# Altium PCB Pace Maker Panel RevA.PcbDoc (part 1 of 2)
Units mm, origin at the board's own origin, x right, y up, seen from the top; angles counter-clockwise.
Board outline 150.47 x 78.27 mm, 2 copper layers (Top Copper, Bottom Copper), stack 1.57 mm thick; 193 components, 124 nets, 564 pads, 154 vias.
Unrouted connection lines stored in the file: 2.
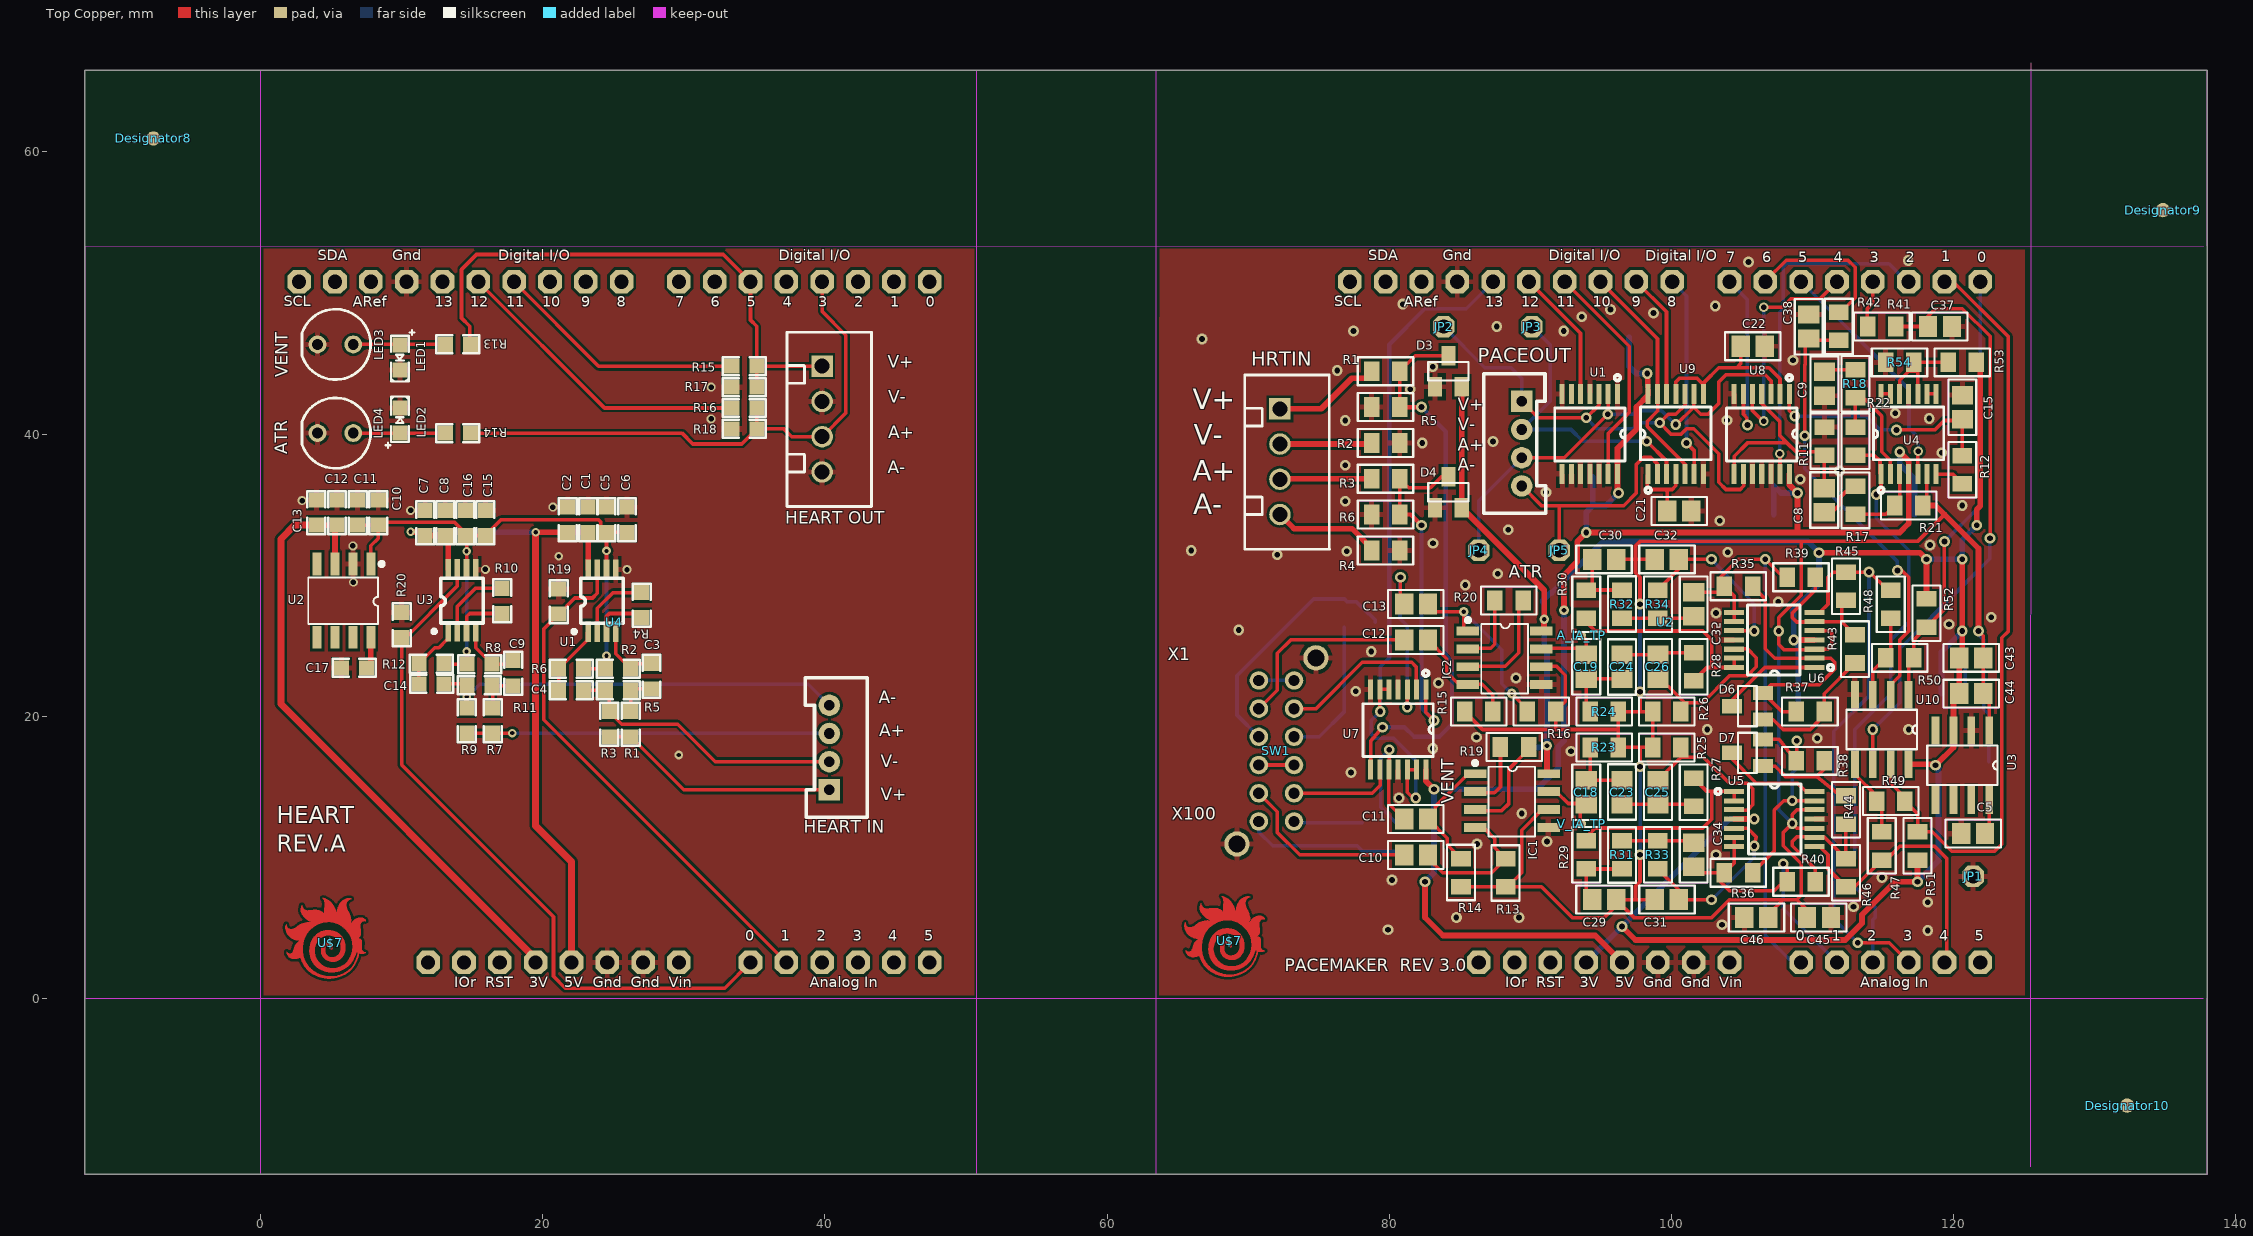
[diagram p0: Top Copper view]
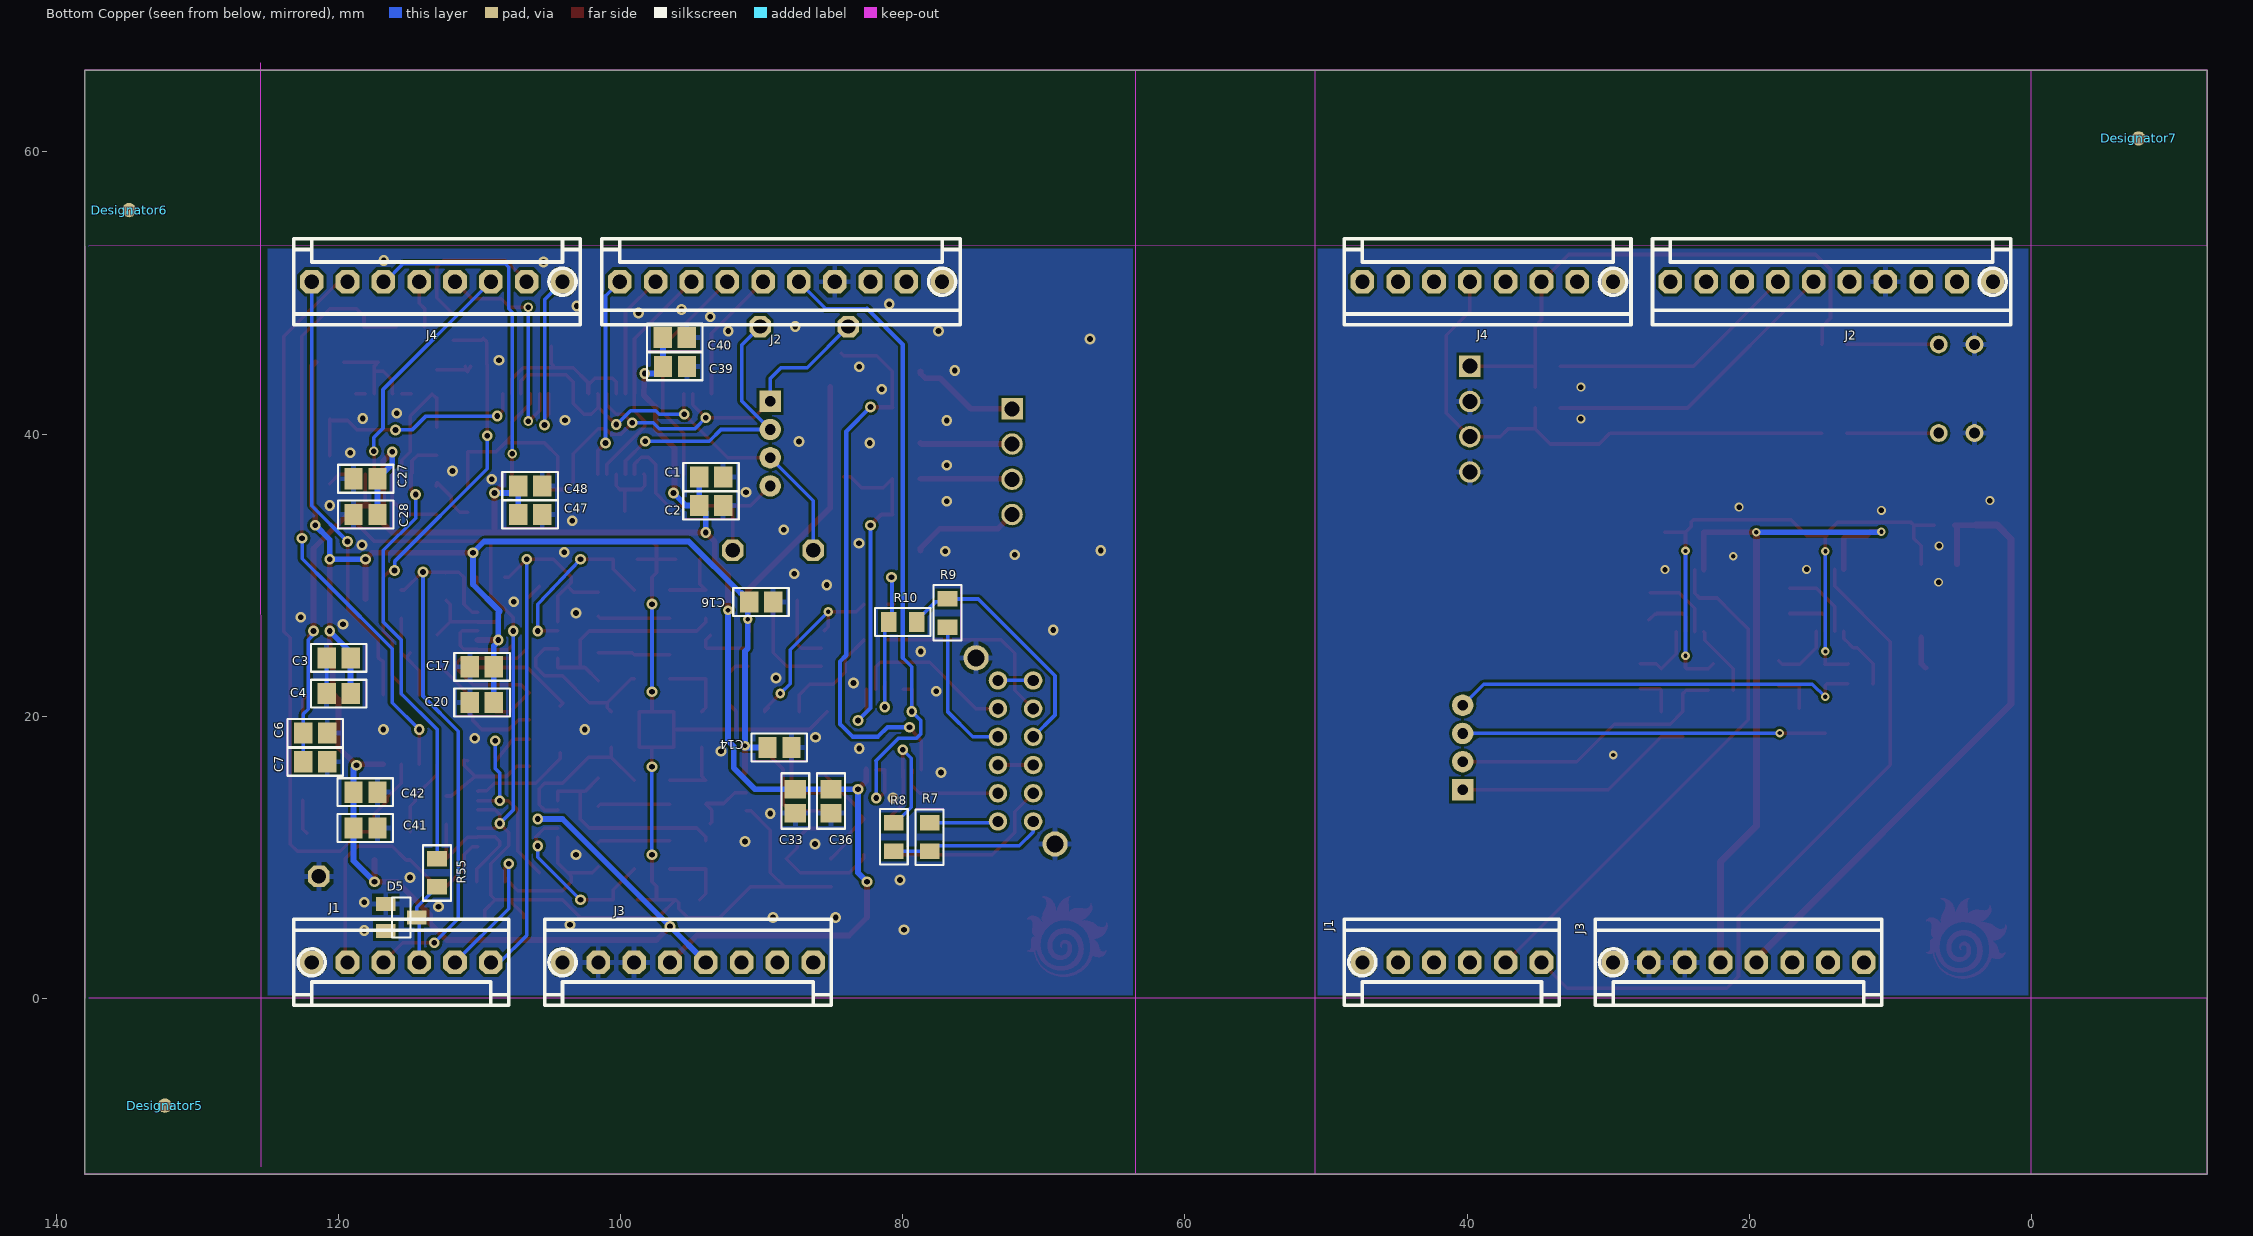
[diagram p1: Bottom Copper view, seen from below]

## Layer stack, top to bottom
Top Mask: solder mask 0.015, Solder Resist, Dk 3.8
Top Copper: signal copper 0.035
Dielectric 1: prepreg 0.1, 2313, Dk 4.05
Core: core 1.3, FR-4, Dk 4.5
Dielectric 2: prepreg 0.1, 2313, Dk 4.05
Bottom Copper: signal copper 0.035
Bottom Mask: solder mask 0.015, Solder Resist, Dk 3.8

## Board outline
-12.471,0 -12.471,53.33 -12.471,65.801 137.998,65.801 137.998,53.33 137.998,0 137.998,-12.471 -12.471,-12.471

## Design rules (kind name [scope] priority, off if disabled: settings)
AssemblyTestPointUsage [All] p1 off:
AssemblyTestpoint [All] p1 off: testpointundercomponent=TRUE minsize=1.016 maxsize=2.54 preferedsize=1.524 minholesize=0 maxholesize=1.016 preferedholesize=0.813 testpointgrid=0.025 usegrid=TRUE gridtolerance=0 allowsidetop=TRUE allowsidebottom=TRUE
Clearance Clearance_poly [InPolygon vs InPolygon] p1: gap=0.254 ignorepadtopadclearanceinfootprint=FALSE
Clearance [All] p2: gap=0.152 ignorepadtopadclearanceinfootprint=FALSE
ComponentClearance [All] p1 off: gap=0.254 collisioncheckmode=3 verticalgap=0.254 showdistances=FALSE
DiffPairsRouting [All] p1 off: maxlimit=0.254 minlimit=0.254 mostfreqgap=0.254 toplayer_minwidth=0.381 toplayer_maxwidth=0.381 toplayer_prefwidth=0.381 bottomlayer_minwidth=0.381 bottomlayer_maxwidth=0.381 bottomlayer_prefwidth=0.381 maxuncoupledlength=12.7
FabricationTestPointUsage [All] p1 off: valid=0 allowmultiple=FALSE
FabricationTestpoint [All] p1 off: side=3 testpointundercomponent=TRUE minsize=1.016 maxsize=2.54 preferedsize=1.524 minholesize=0 maxholesize=1.016 preferedholesize=0.813 testpointgrid=0.025 allowsidetop=TRUE allowsidebottom=TRUE usegrid=TRUE gridtolerance=0
FanoutControl Fanout_BGA [IsBGA] p1 off: bgadir=Out bgaviamode=Centered fanoutstyle=Auto fanoutdirection=Alternating viagrid=0.025 // Fanout_BGA (Default Rule)
FanoutControl Fanout_LCC [IsLCC] p2 off: bgadir=Out bgaviamode=Centered fanoutstyle=Auto fanoutdirection=Alternating viagrid=0.025 // Fanout_LCC (Default Rule)
FanoutControl Fanout_SOIC [IsSOIC] p3 off: bgadir=Out bgaviamode=Centered fanoutstyle=Auto fanoutdirection=Alternating viagrid=0.025 // Fanout_SOIC (Default Rule)
FanoutControl Fanout_Small [(CompPinCount < 5)] p4 off: bgadir=Out bgaviamode=Centered fanoutstyle=Auto fanoutdirection=OutThenIn viagrid=0.025 // Fanout_Small (Default Rule)
FanoutControl Fanout_Default [All] p5 off: bgadir=Out bgaviamode=Centered fanoutstyle=Auto fanoutdirection=Alternating viagrid=0.025 // Fanout_Default (Default Rule)
Height [All] p1 off: minheight=0 maxheight=25.4 prefheight=12.7
HoleSize [All] p1: absolutevalues=TRUE maxlimit=6 minlimit=0.025 maxpercent=80.000 minpercent=20.000
MinimumSolderMaskSliver [All] p1 off: minsoldermaskwidth=0.254
PolygonConnect PolygonConnect_via [IsVia] p1: connectstyle=Direct reliefconductorwidth=0.254 reliefentries=4 polygonreliefangle="90 Angle" airgapwidth=0.254
PolygonConnect [All] p2: connectstyle=Relief reliefconductorwidth=0.381 reliefentries=4 polygonreliefangle="90 Angle" airgapwidth=0.203
RoutingPriority [All] p1 off: routingpriority=0
RoutingTopology [All] p1 off: topology=Shortest
RoutingVias [All] p1: holewidth=0.381 width=0.635 viastyle="Through Hole" minholewidth=0.305 minwidth=0.61 maxholewidth=1.524 maxwidth=2.032
SilkToSilkClearance [All] p1 off: silktosilkclearance=0.254
SilkToSolderMaskClearance [IsPad] p1 off: minsilkscreentomaskgap=0.254 clearancetoexposedcopper=TRUE
SolderMaskExpansion [All] p1: expansion=0.102 istentingtop=FALSE
UnRoutedNet UnRoutedNet_signal [All] p1:
UnpouredPolygon [All] p1 off:
Width [All] p1: maxlimit=2.032 minlimit=0.203 preferedwidth=0.203
10 further rules are at their usual default settings.

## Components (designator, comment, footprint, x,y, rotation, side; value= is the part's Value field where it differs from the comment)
A_IA_TP "TPSTP06R" TP06R 93.662,25.717 r0 top
C1 "*" C0805 93.599,36.957 r180 bottom value=0.1uF
C1 "0.1uF" 0603_N_1MM 23.21,34.812 r270 top value=CL10B104KB8NNNL
C2 "*" C0805 93.599,34.925 r180 bottom value=1uF
C2 "1uF" 0603_N 21.761,34.812 r270 top value=CL10B105KQ8NNNC
C3 "*" C0805 120.015,24.13 r0 bottom value=0.1uF
C3 "3300pF" 0603_N 27.699,21.935 r90 top value=885012006016
C4 "*" C0805 120.015,21.59 r0 bottom value=1uF
C4 "3300pF" 0603_N 22.891,21.834 r180 top value=885012006016
C5 "*" C0805 121.412,11.684 r180 top value=1uF
C5 "0.1uF" 0603_N_1MM 24.511,34.812 r270 top value=CL10B104KB8NNNL
C6 "*" C0805 121.666,18.796 r180 bottom value=0.1uF
C6 "1uF" 0603_N 25.961,34.812 r270 top value=CL10B105KQ8NNNC
C7 "*" C0805 121.666,16.764 r180 bottom value=1uF
C7 "0.1uF" 0603_N_1MM 11.652,34.584 r270 top value=CL10B104KB8NNNL
C8 "*" C0805 110.858,35.306 r270 top value=1uF
C8 "1uF" 0603_N 13.074,34.584 r270 top value=CL10B105KQ8NNNC
C9 "*" C0805 110.871,43.561 r90 top value=1uF
C9 "3300pF" 0603_N 17.892,22.149 r90 top value=885012006016
C10 "*" C0805 81.915,10.16 r0 top value=10uF
C10 "0.1uF" 0603_N_1MM 8.324,35.32 r270 top value=CL10B104KB8NNNL
C11 "*" C0805 81.915,12.7 r0 top value=10uF
C11 "1uF" 0603_N 6.862,35.32 r270 top value=CL10B105KQ8NNNC
C12 "*" C0805 81.915,25.4 r0 top value=10uF
C12 "0.1uF" 0603_N_1MM 5.399,35.32 r270 top value=CL10B104KB8NNNL
C13 "*" C0805 81.915,27.94 r0 top value=10uF
C13 "1uF" 0603_N 3.937,35.32 r270 top value=CL10B105KQ8NNNC
C14 "*" C0805 88.75,17.78 r180 bottom value=0.1uF
C14 "3300pF" 0603_N 12.998,22.288 r180 top value=885012006016
C15 "*" C0805 120.65,41.91 r90 top value=1uF
C15 "0.1uF" 0603_N_1MM 15.919,34.584 r270 top value=CL10B104KB8NNNL
C16 "*" C0805 90.05,28.1 r180 bottom value=1uF
C16 "1uF" 0603_N 14.496,34.584 r270 top value=CL10B105KQ8NNNC
C17 "*" C0805 109.855,23.495 r0 bottom value=0.1uF
C17 "1uF" 0603_N 5.719,23.419 r0 top value=CL10B105KQ8NNNC
C18 "*" C0805 93.98,14.605 r90 top value=10uF
C19 "*" C0805 93.98,23.495 r270 top value=10uF
C20 "*" C0805 109.855,20.955 r0 bottom value=1uF
C21 "*" C0805 100.584,34.544 r0 top value=10uF
C22 "*" C0805 105.791,46.228 r0 top value=10uF
C23 "*" C0805 96.52,14.605 r270 top value=1.5uF
C24 "*" C0805 96.52,23.495 r90 top value=1.5uF
C25 "*" C0805 99.06,14.605 r90 top value=1.5uF
C26 "*" C0805 99.06,23.495 r270 top value=10uF
C27 "*" C0805 118.11,36.83 r0 bottom value=0.1uF
C28 "*" C0805 118.11,34.29 r0 bottom value=1uF
C29 "*" C0805 95.25,6.985 r0 top value=0.1uF
C30 "*" C0805 95.25,31.115 r0 top value=0.1uF
C31 "*" C0805 99.695,6.985 r180 top value=0.039uF
C32 "*" C0805 99.695,31.115 r180 top value=0.022uF
C33 "*" C0805 87.63,13.97 r270 bottom value=0.1uF
C34 "*" C0805 101.6,10.16 r270 top value=0.39uF
C35 "*" C0805 101.6,27.94 r90 top value=0.22uF
C36 "*" C0805 85.09,13.97 r270 bottom value=1uF
C37 "*" C0805 119.062,47.625 r0 top value=1uF
C38 "*" C0805 109.753,47.625 r90 top value=1uF
C39 "*" C0805 96.166,44.801 r180 bottom value=0.1uF
C40 "*" C0805 96.177,46.855 r180 bottom value=1uF
C41 "*" C0805 118.11,12.065 r180 bottom value=0.1uF
C42 "*" C0805 118.11,14.605 r180 bottom value=1uF
C43 "*" C0805 121.285,24.13 r0 top value=0.1uF
C44 "*" C0805 121.285,21.59 r0 top value=1uF
C45 "*" C0805 110.49,5.715 r0 top value=1uF
C46 "*" C0805 106.045,5.715 r180 top value=0.1uF
C47 "*" C0805 106.426,34.29 r180 bottom value=1uF
C48 "*" C0805 106.426,36.322 r180 bottom value=0.1uF
D3 "BAT54S" SOT23 84.201,44.45 r0 top
D4 "BAT54S" SOT23 84.201,35.877 r0 top
D5 "*" SOT23 115.57,5.715 r270 bottom value=BZX84C3V3LT1G
D6 "BAT54S" SOT23 105.41,20.701 r90 top
D7 "BAT54S" SOT23 105.41,17.399 r90 top
Designator5 "Comment" Fiducial_40_100#1 132.334,-7.62 r180 bottom
Designator6 "Comment" Fiducial_40_100#1 134.874,55.88 r180 bottom
Designator7 "Comment" Fiducial_40_100#1 -7.62,60.96 r180 bottom
Designator8 "Comment" Fiducial_40_100#1 -7.62,60.96 r0 top
Designator9 "Comment" Fiducial_40_100#2 134.874,55.88 r180 bottom
Designator10 "Comment" Fiducial_40_100#2 132.334,-7.62 r180 bottom
"HEART IN" "B4B-PH-K-S" B4B-PH-K-S 40.31,15.769 r90 top
"HEART OUT" "B4B-XH-A" B4B-XH-A 39.802,44.813 r270 top value=B4B-XH-A(LF)(SN)
HRTIN "B4B-XH-A" B4B-XH-A 72.263,41.79 r270 top
IC1 "AD8226" SOIC8_SMTC 86.1,15.91 r0 top
IC2 "AD8226" SOIC8_SMTC 85.593,26.04 r0 top
J1 "LHS-06-TS" LHS-00-TS_OUTLINE 121.92,2.54 r0 bottom
J1 "LHS-06-TS" LHS-00-TS_OUTLINE 47.422,2.54 r0 bottom
J2 "LHS-10-TS" LHS-10-TS_OUTLINE 77.216,50.8 r180 bottom
J2 "LHS-10-TS" LHS-10-TS_OUTLINE 2.718,50.8 r180 bottom
J3 "LHS-08-TS" LHS-08-TS_OUTLINE 104.14,2.54 r0 bottom
J3 "LHS-08-TS" LHS-08-TS_OUTLINE 29.642,2.54 r0 bottom
J4 "LHS-08-TS" LHS-08-TS_OUTLINE 104.14,50.8 r180 bottom
J4 "LHS-08-TS" LHS-08-TS_OUTLINE 29.642,50.8 r180 bottom
JP1 "PINHD-1X1" 1X01 121.412,8.636 r0 top
JP2 "PINHD-1X1" 1X01 83.87,47.625 r0 top
JP3 "PINHD-1X1" 1X01 90.12,47.625 r0 top
JP4 "PINHD-1X1" 1X01 86.36,31.75 r0 top
JP5 "PINHD-1X1" 1X01 92.075,31.75 r0 top
LED1 "VLMB1300-GS08" LED_0603 9.855,46.33 r270 top
LED2 "SML-D12V1WT86" LED_0603 9.855,40.068 r90 top
LED3 "151051BS04000" LED_5mm 5.288,46.355 r0 top
LED4 "151051RS11000" LED_5mm 5.288,40.068 r0 top
PACEOUT "B4B-PH-K-S" B4B-PH-K-S 89.408,41.322 r270 top value=B4B-XH-A
R1 "*" R0805 79.756,44.45 r0 top value=59
R1 "75K" 0603_N_RES 26.226,20.31 r270 top value=RC0603FR-0775KL
R2 "*" R0805 79.756,39.37 r0 top value=59
R2 "162K" 0603_N_RES 24.447,23.358 r0 top value=RC0603FR-07162KL
R3 "*" R0805 79.756,36.83 r0 top value=59
R3 "1K" 0603_N_RES 24.717,20.31 r270 top value=RC0603FR-071KL
R4 "*" R0805 79.756,31.75 r0 top value=59
R4 "49.9K" 0603_N_RES 27,28.753 r270 top value=RC0603FR-0749K9L
R5 "*" R0805 79.756,41.91 r0 top value=1M
R5 "49.9K" 0603_N_RES 24.447,21.834 r0 top value=RC0603FR-0749K9L
R6 "*" R0805 79.756,34.29 r0 top value=1M
R6 "162K" 0603_N_RES 21.113,23.358 r0 top value=RC0603FR-07162KL
R7 "*" R0805 78.105,11.43 r90 bottom value=100k
R7 "75K" 0603_N_RES 16.434,20.561 r270 top value=RC0603FR-0775KL
R8 "*" R0805 80.645,11.43 r270 bottom value=1k
R8 "162K" 0603_N_RES 14.623,23.678 r0 top value=RC0603FR-07162KL
R9 "*" R0805 76.835,27.305 r270 bottom value=100k
R9 "1K" 0603_N_RES 14.605,20.561 r270 top value=RC0603FR-071KL
R10 "*" R0805 80.01,26.67 r180 bottom value=1k
R10 "49.9K" 0603_N_RES 17.109,29.055 r270 top value=RC0603FR-0749K9L
R11 "*" R0805 110.871,39.497 r270 top value=5.49k
R11 "49.9K" 0603_N_RES 14.605,22.186 r0 top value=RC0603FR-0749K9L
R12 "*" R0805 120.65,37.465 r270 top value=3.3k
R12 "162K" 0603_N_RES 11.201,23.714 r0 top value=RC0603FR-07162KL
R13 "*" R0805 88.265,8.89 r90 top value=10k
R13 "100" 0603_N_RES 14.852,46.355 r180 top value=RC0603FR-07100RL
R14 "*" R0805 85.1,8.9 r270 top value=10k
R14 "150" 0603_N_RES 14.852,40.068 r180 top value=RC0603FR-07150RL
R15 "*" R0805 86.36,20.32 r0 top value=10k
R15 "100K" 0603_N_RES 33.39,44.813 r0 top value=RC0603FR-07100KL
R16 "*" R0805 90.805,20.32 r0 top value=10k
R16 "100K" 0603_N_RES 33.39,41.846 r0 top value=RC0603FR-07100KL
R17 "*" R0805 113.081,35.306 r90 top value=249k
R17 "1K" 0603_N_RES 33.39,43.329 r0 top value=RC0603FR-071KL
R18 "*" R0805 113.068,43.561 r270 top value=249k
R18 "1K" 0603_N_RES 33.39,40.362 r0 top value=RC0603FR-071KL
R19 "*" R0805 88.9,17.8 r0 top value=1.02k
R19 "49.9K" 0603_N_RES 21.113,29.007 r270 top value=RC0603FR-0749K9L
R20 "*" R0805 88.5,28.2 r0 top value=1.02k
R20 "49.9K" 0603_N_RES 9.982,27.356 r270 top value=RC0603FR-0749K9L
R21 "*" R0805 116.84,34.925 r180 top value=249k
R22 "*" R0805 113.068,39.497 r90 top value=249k
R23 "*" R0805 95.25,17.78 r180 top value=330k
R24 "*" R0805 95.25,20.32 r180 top value=330k
R25 "*" R0805 99.695,17.78 r0 top value=1.4M
R26 "*" R0805 99.695,20.32 r0 top value=330k
R27 "*" R0805 101.6,14.605 r90 top value=715k
R28 "*" R0805 101.6,23.495 r270 top value=715k
R29 "*" R0805 93.98,10.16 r270 top value=39k
R30 "*" R0805 93.98,27.94 r90 top value=22.1k
R31 "*" R0805 96.52,10.16 r90 top value=7.5k
R32 "*" R0805 96.52,27.94 r270 top value=7.5k
R33 "*" R0805 99.06,10.16 r270 top value=133k
R34 "*" R0805 99.06,27.94 r90 top value=133k
R35 "*" R0805 104.775,29.21 r0 top value=4.99k
R36 "*" R0805 104.775,8.89 r0 top value=4.99k
R37 "*" R0805 109.855,20.32 r0 top value=4.99k
R38 "*" R0805 109.855,16.828 r0 top value=4.99k
R39 "*" R0805 109.22,29.845 r0 top value=10k
R40 "*" R0805 109.22,8.255 r0 top value=10k
R41 "*" R0805 114.935,47.625 r180 top value=3.3k
R42 "*" R0805 111.887,47.638 r90 top value=10k
R43 "*" R0805 113.03,24.765 r90 top value=4.99k
R44 "*" R0805 112.395,13.335 r270 top value=4.99k
R45 "*" R0805 112.395,29.21 r90 top value=10k
R46 "*" R0805 112.395,8.89 r270 top value=10k
R47 "*" R0805 114.935,10.795 r270 top value=10k
R48 "*" R0805 115.57,27.94 r90 top value=10k
R49 "*" R0805 115.57,13.97 r180 top value=10M
R50 "*" R0805 116.205,24.13 r180 top value=10M
R51 "*" R0805 117.475,10.795 r270 top value=10k
R52 "*" R0805 118.11,27.305 r90 top value=10k
R53 "*" R0805 120.65,45.085 r0 top value=510k
R54 "*" R0805 116.205,45.085 r0 top value=510k
R55 "*" R0805 113.03,8.89 r90 bottom value=59
SW1 "EG4208" EG4208-PACKAGE 69.215,24.13 r180 top
U1 "CD74HC4066PWR" SOP65P640X110-14N 94.234,40.005 r270 top
U1 "AD8220" MSOP8_0.65mm_DGK 23.211,25.99 r90 top value=AD8220ARMZ-R7
U2 "ARDUINOR3-DIMENSION" ARDUINOR3 58.42,0 r0 top locked
U2 "TLE2426CDR" SOIC8_SMTC 7.798,30.785 r270 top
U3 "TLE2426CDR" SOIC127P600X175-8N 120.65,16.51 r270 top
U3 "AD8220" MSOP8_0.65mm_DGK 13.284,26.007 r90 top value=AD8220ARMZ-R7
U4 "LMV344MT" SOP65P640X110-14N 116.84,40.005 r90 top
U4 "ARDUINO_R3" ARDUINOR3 -16.078,0 r0 top value=n/a
U5 "LMV344MT" SOP65P640X110-14N 107.315,12.7 r0 top
U6 "LMV344MT" SOP65P640X110-14N 107.315,25.4 r180 top
U7 "CD74HC4066PWR" SOP65P640X110-14N 80.645,19.05 r270 top
U8 "CD74HC4066PWR" SOP65P640X110-14N 106.426,40.005 r270 top
U9 "CD74HC4066PWR" SOP65P640X110-14N 100.33,40.005 r90 top
U10 "MCP6547-E/SN" SOIC127P600X175-8N 114.935,19.05 r270 top
U$7 "" FIREBALL 68.671,4.067 r0 top
U$7 "" FIREBALL 4.928,3.937 r0 top
V_IA_TP "TPSTP06R" TP06R 93.662,12.383 r0 top

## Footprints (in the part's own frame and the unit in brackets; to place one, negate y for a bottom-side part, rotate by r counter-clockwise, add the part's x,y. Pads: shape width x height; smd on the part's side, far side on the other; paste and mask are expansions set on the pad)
1X01 [mil] "1X01"
  oct 60x60 / inner round 0 / far side oct 60x60 hole 40: 1(0,0)
0603_N [mil]
  rect 42x42 smd mask+0: 1(0,0) 2(70,0)
  silkscreen extent -25,-25 95,25, body extent 3,-16 66,16, height 19
0603_N_1MM [mil] "Full height"
  rect 42x42 smd mask+0: 1(0,0) 2(70,0)
  silkscreen extent -25,-25 95,25, body extent 3,-16 66,15, height 31
0603_N_RES [mil]
  rect 42x42 smd mask+0: 1(0,0) 2(70,0)
  silkscreen extent -25,-25 95,25, body extent 3,-16 66,16, height 19
ARDUINOR3 [mil] "ARDUINOR3"
  oct 66x66 / inner round 0 / far side oct 66x66 hole 39.37: 3V(1400,100) 5V(1500,100) A0(2000,100) A1(2100,100) A2(2200,100) A3(2300,100) A4(2400,100) A5(2500,100) AREF(940,2000) D0(2500,2000) D1(2400,2000) D2(2300,2000) D3(2200,2000) D4(2100,2000) D5(2000,2000) D6(1900,2000) D7(1800,2000) D8(1640,2000) D9(1540,2000) D10(1440,2000) D11(1340,2000) D12(1240,2000) D13(1140,2000) GND(1040,2000) GND1(1700,100) GND2(1600,100) IOREF(1200,100) RESERVED(1100,100) RESET(1300,100) SDA(840,2000) VIN(1800,100)
  oct 66x66 hole 39.37: SCL(740,2000)
B4B-PH-K-S [mil]
  rect 60x60 / inner round 60 / far side rect 60x60 hole 30: 1(-39.37,0)
  round 60 hole 30: 2(39.37,0) 3(118.11,0) 4(196.85,0)
  silkscreen extent -116,-106 274,67, body extent -116,-110 274,67, height 236
B4B-XH-A [mil]
  rect 60x60 hole 42: 1(0,0)
  round 60 hole 42: 2(98.43,0) 3(196.85,0) 4(295.28,0)
  silkscreen extent -94,-98 392,138, body extent -96,-94 392,132, height 276
C0805 [mm] "C0805"
  rect 1.3x1.5 smd: 1(-0.85,0) 2(0.85,0)
  Top Copper keep-out lines w0.051: 1.973,-0.983 -1.973,-0.983 -1.973,0.983 1.973,0.983 1.973,-0.983
  silkscreen extent -1.98,-0.99 1.96,0.99
EG4208-PACKAGE [mil] "EG4208-PACKAGE"
  round 51.5 / inner round 0 / far side round 51.5 hole 31.5: 1(-61.02,456.69) 2(-61.02,377.95) 3(-61.02,299.21) 4(-61.02,220.47) 5(-61.02,141.73) 6(-61.02,62.99) 7(-159.45,456.69) 8(-159.45,377.95) 9(-159.45,299.21) 10(-159.45,220.47) 11(-159.45,141.73) 12(-159.45,62.99)
  round 70.86 / inner round 0 / far side round 70.86 hole 47.24: NC1(0,519.68) NC2(-220.47,0)
Fiducial_40_100#1 [mil] "40 copper 120 clearance"
  round 40 smd paste-78.74 mask+30: 0(0,0)
Fiducial_40_100#2 [mil] "40 copper 120 clearance"
  round 40 smd far side paste-78.74 mask+30: 0(0,0)
FIREBALL [mm] "FIREBALL"
  Top Copper drawing of 1562 lines, arcs and shapes, not listed
LED_5mm [mm]
  round 1.27 hole 0.762: A(1.265,0) K(-1.275,0)
  silkscreen extent -2.38,-2.5 2.5,2.5
LED_0603 [mil]
  rect 42x42 smd mask+0: A(0,0) K(70,0)
  silkscreen extent -41,-25 102,40, body extent 2,-18 69,18, height 35
LHS-00-TS_OUTLINE [mm]
  silkscreen extent -13.97,-3.05 1.27,3.05, body extent -14.1,-3.17 1.4,3.17, height 10
LHS-08-TS_OUTLINE [mm]
  silkscreen extent -19.05,-3.05 1.27,3.05
LHS-10-TS_OUTLINE [mm]
  silkscreen extent -24.13,-3.05 1.27,3.05
MSOP8_0.65mm_DGK [mm]
  rect 1.45x0.4 smd: 1(0,0) 2(0,-0.65) 3(0,-1.3) 4(0,-1.95) 5(4.4,-1.95) 6(4.4,-1.3) 7(4.4,-0.65) 8(4.4,0)
  silkscreen extent -0.14,-2.48 3.77,1.14, body extent -0.27,-2.5 4.67,0.6, height 1.1
R0805 [mm] "R0805"
  rect 1.1x1.4 smd: 1(-1,0) 2(1,0)
  Top Copper keep-out lines w0.051: -1.973,-0.983 -1.973,0.983 1.973,0.983 1.973,-0.983 -1.973,-0.983
  silkscreen extent -1.98,-0.99 1.96,0.99
SOIC8_SMTC [mil]
  rect 63x25 smd: 1(0,0) 2(0,-50) 3(0,-100) 4(0,-150) 5(205,-150) 6(205,-100) 7(205,-50) 8(205,0)
  silkscreen extent -5,-175 167,35, body extent -16,-171 220,21, height 67
SOIC127P600X175-8N [mil] "SOIC127P600X175-8N"
  rect 78x22 smd: 1(-97,75) 2(-97,25) 3(-97,-25) 4(-97,-75) 5(97,-75) 6(97,-25) 7(97,25) 8(97,75)
  silkscreen extent -55,-98 55,98
SOP65P640X110-14N [mil] "SOP65P640X110-14N"
  rect 56x14 smd: 1(-112,77) 2(-112,51) 3(-112,26) 4(-112,0) 5(-112,-26) 6(-112,-51) 7(-112,-77) 8(112,-77) 9(112,-51) 10(112,-26) 11(112,0) 12(112,26) 13(112,51) 14(112,77)
  silkscreen extent -165,-98 75,98
SOT23 [mm] "SOT23"
  rect 1x1.4 smd: 1(-0.95,-1.1) 2(0.95,-1.1) 3(0,1.1)
  silkscreen extent -1.42,-0.66 1.42,0.66
TP06R [mm] "TP06R"
  rrect100% 0.6x0.6 smd paste+0: TP(0,0)

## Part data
A_IA_TP V_IA_TP: "TEST PIN"
C1 C2 C3 C4 C5 C6 C7 C8 C9 C10 C11 C12 C13 C14 C15 C16 C17 C18 C19 C20 C21 C22 C23 C24 C25 C26 C27 C28 C29 C30 C31 C32 C33 C34 C35 C36 C37 C38 C39 C40 C41 C42 C43 C44 C45 C46 C47 C48: library part C-USC0805, "CAPACITOR, American symbol"
C1 C5 C7 C10 C12 C15: library part CAP, "CAP CER 0.1UF 50V X7R 0603", Manufacturer=Samsung
C2 C6 C8 C11 C13 C16 C17: library part CAP, "CAP CER 1UF 6.3V X7R 0603", Manufacturer=Samsung
C3 C4 C9 C14: library part CAP, "CAP CER 3300PF 10V C0G/NP0 0603", Manufacturer="Würth Elektronik"
D3 D4 D6 D7: "Schottky Diodes   Pin connection corrected 2011-05-04 Source: Fairchild .. BAT54.pdf"
D5: library part ZENER-DIODESOT23, "Z-Diode"
"HEART IN": library part "Header 4", "CONN HEADER VERT 4POS 2MM", Manufacturer=JST
"HEART OUT": library part "Header 4", "CONN HEADER VERT 4POS 2.5MM", Manufacturer=JST
HRTIN PACEOUT: library part CON4, "Conn mFit 2x2M Strgt.", Manufacturer=Molex
IC1 IC2: "Wide Supply Range, Rail-to-Rail Output Instrumentation Amplifier", MPN=AD623ARZ.
J1 J1: library part "SIP Header 6 Outline", "CONN HEADER VERT 6 POS 2.54MM", Manufacturer="Adam Tech"
J2 J2: library part "SIP Header 10 Outline", "CONN HEADER VERT 10POS 2.54MM", Manufacturer="Adam Tech"
J3 J3 J4 J4: library part "SIP Header 8 Outline", "Header, 8-Pin", Manufacturer="Adam Tech"
JP1 JP2 JP3 JP4 JP5: "PIN HEADER"
LED1: library part LED_1, "LED BLUE HIGHBRIGHT 0603 SMD", Manufacturer=Vishay
LED2: library part LED_1, "Red LED 2.2V 0603", Manufacturer="Rohm Semiconductor"
LED3: library part LED_1, "LED BLUE DIFFUSED 5MM ROUND T/H", Manufacturer="Würth Elektronik"
LED4: library part LED_1, "LED RED DIFFUSED 5MM ROUND T/H", Manufacturer="Würth Elektronik"
R1 R2 R3 R4 R5 R6 R7 R8 R9 R10 R11 R12 R13 R14 R15 R16 R17 R18 R19 R20 R21 R22 R23 R24 R25 R26 R27 R28 R29 R30 R31 R32 R33 R34 R35 R36 R37 R38 R39 R40 R41 R42 R43 R44 R45 R46 R47 R48 R49 R50 R51 R52 R53 R54 R55: library part R-US_R0805, "RESISTOR, American symbol"
R1 R7: library part RES1, "RES SMD 75K OHM 1% 1/10W 0603", Manufacturer=Yageo
R2 R6 R8 R12: library part RES1, "RES SMD 162K OHM 1% 1/10W 0603", Manufacturer=Yageo
R3 R9 R17 R18: library part RES1, "RES SMD 1K OHM 1% 1/10W 0603", Manufacturer=Yageo
R4 R5 R10 R11 R19 R20: library part RES1, "RES SMD 49.9K OHM 1% 1/10W 0603", Manufacturer=Yageo
R13: library part RES1, "RES SMD 100 OHM 1% 1/10W 0603", Manufacturer=Yageo
R14: library part RES1, "RES SMD 150 OHM 1% 1/10W 0603", Manufacturer=Yageo
R15 R16: library part RES1, "RES SMD 100K OHM 1% 1/10W 0603", Manufacturer=Yageo
U1 U3: "IC INST AMP 1 CIRCUIT 8MSOP", Manufacturer="Analog Devices Inc."
U2: "This is a new object for the new Arduino R3 - with extra pins that you may want to use (such as IOref, and duplicated A4/A5"
U2: library part TLE2426, "IC VREF GND REF 2.0V 1% 8SOIC", Manufacturer="Texas Instruments"
U3: "Precision Virtual Ground"
U4: "Arduino R3 Shield", Manufacturer=n/a
U10: "Open-Drain Output Sub-Microamp Comparators"
U$7 U$7: library part FIREBALL

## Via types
v1: diameter 0.762/0.762 (per signal layer), hole 0.406, Top Copper to Bottom Copper, 126 vias
v2: diameter 0.61, hole 0.305, Top Copper to Bottom Copper, 10 vias
v3: diameter 0.635, hole 0.381, Top Copper to Bottom Copper, 9 vias
v4: diameter 0.686, hole 0.33, Top Copper to Bottom Copper, 5 vias
v5: diameter 0.686, hole 0.381, Top Copper to Bottom Copper, 4 vias

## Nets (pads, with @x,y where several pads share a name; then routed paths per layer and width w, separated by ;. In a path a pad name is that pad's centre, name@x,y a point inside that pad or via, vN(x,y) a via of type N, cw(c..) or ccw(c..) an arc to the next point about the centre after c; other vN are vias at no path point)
3V3: C12.2@5.399,33.542 C13.2@3.937,33.542 U2.3 U4.3V | length 44.7
  Top Copper w0.406: C13.2@3.937,33.542 C12.2@5.399,33.542 5.258,33.4 U2.3@5.258,30.785
  Top Copper w0.508: C13.2@3.937,33.542 2.401,33.542 1.422,32.563 1.422,20.853 19.482,2.794 U4.3V@19.482,2.54
5V0: C1.2@23.21,33.034 C2.2@21.761,33.034 C7.2@11.652,32.806 C8.2@13.074,32.806 U1.8@23.21,30.39 U3.8@13.284,30.406 U4.5V | length 51.9
  Top Copper w0.406: v2(10.617,33.071) 10.631,33.057 11.401,33.057 C7.2@11.652,32.806 C8.2@13.074,32.806 13.284,32.596 U3.8@13.284,30.406 ; v2(19.482,33.034) C2.2@21.761,33.034 C1.2@23.21,33.034 U1.8@23.21,30.39
  Top Copper w0.508: v2(19.482,33.034) 19.482,12.217 22.022,9.677 U4.5V@22.022,2.54
  Bottom Copper w0.406: v2(10.617,33.071) 10.654,33.034 v2(19.482,33.034)
+3V3: C3.1@119.165,24.13 C4.1@119.165,21.59 C14.1@89.6,17.78 C16.1@90.9,28.1 C17.1@109.005,23.495 C20.1 C41.1 C42.1 C43.1 C44.1 D3.2 D4.2 IC1.8 IC2.8 R51.2 R52.2 R53.2 U2.3V U3.3@120.015,18.974 U5.4 U6.4 U10.8 | length 170.2
  Top Copper w0.406: D3.2@85.151,43.35 D4.2@85.151,34.777 86.856,33.072 91,28.928 v4@91,26.9 ; IC2.8@90.993,26.04 v4(90.993,26.87) ; v4(91.2,17.9) 91.2,16.01 IC1.8@91.3,15.91 ; v1(96.52,5.08) 97.472,4.127 112.348,4.127 113.53,5.31 113.53,5.92 115.865,8.255 v1(117.475,8.255) R51.2@117.475,9.795 ; U5.4@104.47,12.7 v1(105.886,12.7) ; v1(108.7,25.4) U6.4@110.16,25.4 ; v1(110.49,31.591) 117.634,31.591 v1(118.11,31.115) R52.2@118.11,28.305 ; U10.8@116.84,16.586 v1@118.821,16.586 ; v1(118.745,16.51) v1@118.821,16.586 ; v1(120.65,31.115) v1(120.65,26.035) 120.65,24.345 C43.1@120.435,24.13 C44.1@120.435,21.59 120.015,21.17 U3.3@120.015,18.974 120.015,17.78 v1@118.821,16.586 ; R53.2@121.65,45.085 121.92,44.815 121.92,34.9 121.666,34.646 v1(121.666,33.528)
  Bottom Copper w0.406: C14.1@89.6,17.78 91.28,17.78 v4@91.3,17.8 ; v4(91.2,17.9) 91.2,24.6 91,24.8 91,26.9 91,28 C16.1@90.9,28.1 90.9,28.2 91.423,28.723 91.523,28.723 95.185,32.385 109.696,32.385 v1(110.49,31.591) 110.49,29.337 108.585,27.432 108.7,27.317 v1(108.7,25.4) 108.7,25.285 109.005,24.98 C17.1@109.005,23.495 C20.1@109.005,20.955 ; U2.3V@93.98,2.54 v1(96.52,5.08) 104.14,12.7 v1(105.886,12.7) ; v1(117.475,8.255) 118.96,9.74 C41.1@118.96,12.065 C42.1@118.96,14.605 118.96,16.295 v1(118.745,16.51) ; v1(118.11,31.115) v1(120.65,31.115) 120.65,32.512 v1(121.666,33.528) ; C4.1@119.165,21.59 C3.1@119.165,24.13 119.165,24.55 v1(120.65,26.035)
+5V: C1.1@94.449,36.957 C2.1@94.449,34.925 C27.1 C28.1 C33.1 C36.1 C39.1 C40.1 C47.1 C48.1 U1.14 U2.5V U4.4 U7.14 U8.14 U9.14 | length 114.8
  Top Copper w0.406: v1(82.55,8.255) 82.55,5.715 83.82,4.445 94.615,4.445 U2.5V@96.52,2.54 ; U7.14@82.601,15.504 U7.14@82.601,16.205 82.601,15.404 v1(83.185,14.82) ; v4(92.4,27.5) 92.4,30 93.345,30.945 93.345,32.385 v1(93.98,33.02) 108.966,33.02 ; v1(96.266,35.814) 96.19,35.89 U1.14@96.19,37.16 96.19,38.99 97.536,40.336 97.536,41.91 98.374,42.748 U9.14@98.374,42.85 98.386,42.861 v1(98.31,44.293) ; U8.14@108.382,37.16 108.382,36.398 v1(108.966,35.814) 108.966,33.02 ; v1(116.205,38.735) 116.84,38.1 U4.4@116.84,37.16 116.84,33.655 116.205,33.02 108.966,33.02
  Bottom Copper w0.406: v1(82.55,8.255) 83.185,8.89 v1(83.185,14.82) ; v1@83.285,14.82 C36.1@85.09,14.82 C33.1@87.63,14.82 90.5,14.82 92,16.32 92,17.852 92.4,18.252 v4(92.4,27.5) ; v1(93.98,33.02) 93.98,34.456 C2.1@94.449,34.925 ; C1.1@94.449,36.957 C2.1@94.449,34.925 ; v1(96.266,35.814) 95.377,34.925 C2.1@94.449,34.925 ; C40.1@97.027,46.855 97.016,46.844 C39.1@97.016,44.801 97.524,44.293 v1(98.31,44.293) ; C47.1@107.276,34.29 C48.1@107.276,36.322 107.784,35.814 v1(108.966,35.814) ; v1(116.205,38.735) 116.205,37.885 C27.1@117.26,36.83 C28.1@117.26,34.29
ADC0: R20.2@9.982,25.578 U3.7@13.934,30.406 U4.A0 | length 50
  Top Copper w0.254: U3.7@13.934,30.406 13.934,29.225 9.982,25.273 9.982,16.535 20.752,5.766 20.752,1.549 21.59,0.711 32.893,0.711 U4.A0@34.722,2.54
ADC1: R19.2@21.113,27.229 U1.7@23.861,30.39 U4.A1 | length 37.3
  Top Copper w0.254: U1.7@23.861,30.39 23.861,28.712 23.52,28.372 22.256,28.372 R19.2@21.113,27.229 20.066,26.182 20.066,19.736 U4.A1@37.262,2.54
ATR+: "HEART IN.3" R7.2@16.434,18.783 R9.2@14.605,18.783 | length 25.7
  Top Copper w0.254: R9.2@14.605,18.783 R7.2@16.434,18.783 17.818,18.783 v2(17.831,18.796)
  Bottom Copper w0.254: v2(17.831,18.796) 40.283,18.796 40.31,18.769
ATR-: "HEART IN.4" C14.1@12.998,22.288 R9.1@14.605,20.561 R11.1@14.605,22.186 | length 29.2
  Top Copper w0.254: C14.1@12.998,22.288 14.504,22.288 R11.1@14.605,22.186 v2(14.605,21.361)
  Bottom Copper w0.254: v2(14.605,21.361) 15.513,22.269 38.81,22.269 40.31,20.769
ATR_NAT: "HEART OUT.3" R14.1@14.852,40.068 R16.2@35.168,41.846 R18.2@35.168,40.362 U4.D3 | length 39.8
  Top Copper w0.254: R14.1@14.852,40.068 29.859,40.068 30.632,39.294 34.1,39.294 R18.2@35.168,40.362 ; R16.2@35.168,41.846 R18.2@35.168,40.362 ; U4.D3@39.802,50.8 39.802,48.692 41.478,47.015 41.478,41.489 39.802,39.813 37.642,39.813 37.093,40.362 R18.2@35.168,40.362
GND: "HEART OUT.2" "HEART OUT.4" C1.1@23.21,34.812 C1.2@92.749,36.957 C2.1@21.761,34.812 C2.2@92.749,34.925 C3.2@120.865,24.13 C4.2@120.865,21.59 C5.1@24.511,34.812 C5.2@120.562,11.684 C6.1@25.961,34.812 C6.2@120.816,18.796 C7.1@11.652,34.584 C7.2@120.816,16.764 C8.1@13.074,34.584 C9.1@110.871,42.711 C10.1@8.324,35.32 C11.1@6.862,35.32 C12.1@5.399,35.32 C13.1@3.937,35.32 C14.2@87.9,17.78 C15.1@15.919,34.584 C15.2@120.65,42.76 C16.1@14.496,34.584 C16.2@89.2,28.1 C17.1@5.719,23.419 C17.2@110.705,23.495 C20.2 C21.2 C22.2 C27.2 C28.2 C33.2 C36.2 C37.2 C38.2 C39.2 C40.2 C41.2 C42.2 C45.2 C46.2 C47.2 C48.2 D3.1 D4.1 D5.1 IC1.5 IC2.5 JP1.1 LED1.K LED2.K LED3.K LED4.K R2.2@80.756,39.37 R4.2@80.756,31.75 R5.1@78.756,41.91 R6.1@78.756,34.29 R11.1@110.871,40.497 R17.1@33.39,43.329 R18.1@33.39,40.362 R19.1@21.113,29.007 R20.1@9.982,27.356 R54.1 SW1.NC1 SW1.NC2 U1.1@96.19,42.85 U1.4@94.234,42.85 U1.5@25.161,30.39 U1.7@92.278,42.85 U1.8@92.278,37.16 U1.9 U1.10 U1.11 U1.12 U2.2 U2.GND U2.GND1 U2.GND2 U3.2@121.285,18.974 U3.5@15.235,30.406 U4.11 U4.GND U4.GND1 U4.GND2 U5.11 U6.11 U7.4 U7.7 U7.11 U8.7 U8.10 U8.11 U8.12 U9.7 U10.4 | length 2.5
  Bottom Copper w0.254: C4.2@120.865,21.59 C3.2@120.865,24.13
  other v1: 118.2,4.8 79.93,4.842 103.6,5.2 84.772,5.715 89.218,5.715 112.93,6.48 118.2,6.8 80.2,8.382 114.953,8.555 103.188,10.16 86.233,10.922 91.2,11.1 89.4,13.1 80.7,14.2 77.3,16 92.9,17.5 83.1,17.7 110.36,18.433 86.2,18.5 102.552,19.05 116.84,19.05 77.635,21.762 83.502,22.352 89,22.7 78.74,24.575 69.342,26.098 119.697,26.511 122.7,27 103.188,27.305 107.6,28.1 85.4,29.3 87.7,30.1 72.072,31.432 104.013,31.623 76.994,31.686 65.977,31.75 118.364,32.131 83.121,32.258 88.456,33.21 103.454,33.858 120.65,34.925 76.898,35.242 91.123,35.877 109.156,36.792 111.938,37.376 76.898,37.782 119.189,38.672 82.359,39.37 87.376,39.472 76.898,40.957 103.962,40.97 118.3,41.1 115.887,41.465 81.502,43.18 76.327,44.514 83.09,44.767 108.636,45.237 66.739,46.736 77.47,47.307 92.392,47.307 87.63,47.625 93.662,48.323 98.742,48.578 95.694,48.831 103.124,49.085 80.962,49.212 105.486,52.197 116.815,52.299
  other v2: 29.642,17.243 21.113,31.344
  other v3: 6.553,29.489 15.919,30.406 25.961,30.39 6.528,32.069 10.617,34.584 20.701,34.812 2.921,35.281 31.928,41.072 31.928,43.329
NetA_IA_TP_TP: A_IA_TP.TP C19.1 IC2.7 | length 4
  Top Copper w0.254: IC2.7@91,24.8 93.908,24.8 93.98,24.872 93.98,25.4 A_IA_TP.TP@93.662,25.717
NetC3_1: C3.1@27.699,21.935 R1.1@26.226,20.31 R5.2@26.226,21.834 | length 3
  Top Copper w0.254: R1.1@26.226,20.31 R5.2@26.226,21.834 26.327,21.935 C3.1@27.699,21.935
NetC3_2: C3.2@27.699,23.713 R2.2@26.226,23.358 U1.4@25.161,25.99 | length 4.7
  Top Copper w0.254: U1.4@25.161,25.99 25.161,24.422 R2.2@26.226,23.358 26.581,23.713 C3.2@27.699,23.713
NetC4_2: C4.2@21.113,21.834 R6.1@21.113,23.358 U1.1@23.21,25.99 | length 5
  Top Copper w0.254: C4.2@21.113,21.834 R6.1@21.113,23.358 23.137,25.382 23.137,25.917 U1.1@23.21,25.99
NetC5_1: C5.1@122.262,11.684 U3.8@122.555,14.046 | length 2.5
  Top Copper w0.254: C5.1@122.262,11.684 122.555,11.977 U3.8@122.555,14.046
NetC6_1: C6.1@122.516,18.796 C7.1@122.516,16.764 C29.2 C30.2 C31.2 C32.2 C43.2 C44.2 C45.1 C46.1 IC1.6 IC2.6 R13.1@88.265,7.89 R14.2@85.1,7.9 R15.1@85.36,20.32 R16.2@91.805,20.32 R21.1 R23.1 R24.1 R25.1 R26.1 U3.1@122.555,18.974 U4.6 U5.10 U5.12 U6.3 U6.5 | length 184.1
  Top Copper w0.254: R14.2@85.1,7.9 88.255,7.9 R13.1@88.265,7.89 ; R15.1@85.36,20.32 86.63,19.05 91.805,19.05 ; IC2.6@91,23.53 91.87,23.53 92.5,22.9 92.5,21.015 R16.2@91.805,20.32 91.805,19.05 ; IC1.6@91.1,13.3 90.8,13.3 89.4,11.9 89.4,8.9 88.39,7.89 R13.1@88.265,7.89 ; C30.2@96.1,31.115 97.472,31.115 ; v1(97.79,10.16) 97.79,8.255 97.472,7.938 97.472,6.985 ; v1(97.79,21.725) 97.79,20.32 ; v1(97.79,27.94) 97.79,29.845 97.472,30.162 97.472,31.115 ; v1(97.8,16.4) 97.8,17.77 97.79,17.78 ; C31.2@98.845,6.985 97.472,6.985 ; C32.2@98.845,31.115 97.472,31.115 ; C46.1@106.895,5.715 106.895,5.93 107.95,6.985 ; C45.1@109.64,5.715 109.64,6.247 108.902,6.985 ; U5.10@110.16,12.04 108.928,12.04 v1(108.585,12.383) ; U5.12@110.16,13.36 108.928,13.36 108.585,13.018 v1(108.585,12.383) ; U6.5@110.16,26.06 111.24,26.06 111.4,25.9 111.4,25 111.14,24.74 U6.3@110.16,24.74 110.134,24.714 108.001,24.714 107.632,25.082 v1(107.632,26.035) 107.632,26.987 109.22,28.575 109.22,32.385 ; R21.1@117.84,34.925 118.135,35.265 U4.6@118.135,37.16 ; 119.38,34.29 117.475,32.385 109.22,32.385 ; v1(121.793,26.035) 122.135,25.693 C43.2@122.135,24.13 C44.2@122.135,21.59 122.555,21.17 U3.1@122.555,18.974 ; R13.1@88.265,7.89 90.805,7.89 92.98,5.715 95.25,5.715 95.885,6.35 95.885,6.77 C29.2@96.1,6.985 ; 91.805,19.05 96.25,19.05 ; C29.2@96.1,6.985 97.37,5.715 102.87,5.715 104.14,6.985 107.95,6.985 ; C29.2@96.1,6.985 97.472,6.985 ; 96.25,19.05 R24.1@96.25,20.32 97.79,20.32 ; 96.25,19.05 R23.1@96.25,17.78 97.79,17.78 ; 97.472,31.115 97.472,32.067 97.79,32.385 109.22,32.385 ; 97.79,17.78 R25.1@98.695,17.78 R26.1@98.695,20.32 97.79,20.32 ; 107.95,6.985 108.902,6.985 ; v1(108.585,12.383) 107.95,11.747 107.95,10.795 109.22,9.525 109.22,7.302 108.902,6.985
  Top Copper w0.406: R21.1@117.84,34.925 118.745,34.925 119.38,34.29 121.793,31.877 v1(121.793,26.035)
  Bottom Copper w0.254: v1(97.79,10.16) 97.8,10.17 v1(97.8,16.4) ; v1(97.79,21.725) 97.79,27.76 97.7,27.85 v1(97.79,27.94) ; v1(107.632,26.035) 107.632,13.335 v1(108.585,12.383) ; v1(121.793,26.035) 121.793,25.781 122.174,25.4 122.174,20.486 122.516,20.144 C6.1@122.516,18.796 C7.1@122.516,16.764
NetC8_1: C8.1@110.858,36.156 R11.2@110.871,38.497 U8.4 U8.8 | length 15.4
  Top Copper w0.254: U8.8@104.47,37.16 104.47,38.43 105.41,39.37 108.22,39.37 ; U8.4@106.426,42.85 106.426,42.164 107.696,40.894 107.696,39.894 108.22,39.37 ; C8.1@110.858,36.156 R11.2@110.858,38.738 ; R11.2@110.871,38.497 R11.2@110.858,38.738 ; 108.22,39.37 108.852,38.738 R11.2@110.858,38.738
NetC8_2: C8.2@110.858,34.456 R17.2@113.081,36.306 | length 3.6
  Top Copper w0.254: C8.2@110.858,34.456 111.418,34.456 112.014,35.052 112.014,35.535 113.039,36.56 R17.2@113.081,36.306
NetC9_1: C9.1@17.892,22.149 R7.1@16.434,20.561 R11.2@16.383,22.186 | length 3.1
  Top Copper w0.254: R11.2@16.383,22.186 R11.2@16.42,22.149 ; R7.1@16.434,20.561 16.434,22.136 R11.2@16.42,22.149 ; C9.1@17.892,22.149 R11.2@16.42,22.149
NetC9_2: C9.2 R8.2@16.401,23.678 R18.1@113.068,44.561 U3.4@15.235,26.006 | length 7.6
  Top Copper w0.254: U3.4@15.235,26.006 15.235,24.845 R8.2@16.401,23.678 17.643,23.678 C9.2@17.892,23.927 ; C9.2@110.64,44.815 C9.2@110.871,44.411 ; C9.2@111.021,44.815 C9.2@110.871,44.411 ; R18.1@113.068,44.561 111.021,44.561 C9.2@110.871,44.411
NetC10_1: C10.1@81.065,10.16 SW1.2 | length 13
  Top Copper w0.254: SW1.2@70.765,14.53 72.072,13.222 72.072,11.747 73.66,10.16 C10.1@81.065,10.16
NetC10_2: C10.2@82.765,10.16 IC1.4 R13.2@88.265,9.89 | length 10.2
  Top Copper w0.254: C10.2@82.765,10.16 82.765,9.935 83.8,8.9 84.419,8.9 85.781,8.9 87.275,8.9 R13.2@88.265,9.89 87.5,10.655 87.5,11.3 86.77,12.03 IC1.4@85.9,12.03
NetC11_1: C11.1@81.065,12.7 R8.1@80.645,12.43 U7.10 | length 12.6
  Top Copper w0.254: v1(80.01,17.621) 80.01,15.625 U7.10@79.985,16.205 79.985,13.781 C11.1@81.065,12.7
  Bottom Copper w0.254: v1(80.01,17.621) 79.4,17.011 79.4,13.525 80.072,12.853 80.495,12.43 R8.1@80.645,12.43
NetC11_2: C11.2@82.765,12.7 IC1.1 R14.1@85.1,9.9 | length 8.7
  Top Copper w0.254: R14.1@85.1,9.9 85.09,9.9 84.117,10.873 84.117,11.348 C11.2@82.765,12.7 83.288,13.223 83.288,13.588 85.61,15.91 IC1.1@86.1,15.91
NetC12_1: C12.1@81.065,25.4 SW1.5 | length 13.8
  Top Copper w0.254: SW1.5@70.765,20.53 72.072,21.837 72.072,24.447 73.025,25.4 C12.1@81.065,25.4
NetC12_2: C12.2@82.765,25.4 IC2.4 R15.2@87.36,20.32 | length 8
  Top Copper w0.254: C12.2@82.765,25.4 84.1,24.065 84.1,23.1 84.94,22.26 85.8,22.26 86.6,22.26 87.36,21.5 R15.2@87.36,20.32
NetC13_1: C13.1@81.065,27.94 R10.1@81.01,26.67 U7.3 | length 14.2
  Top Copper w0.254: v1(80.804,29.845) 80.804,28.702 80.804,28.099 80.645,27.94 C13.1@81.065,27.94 ; v1(81.28,20.637) 81.28,22.475 U7.3@81.305,21.895
  Bottom Copper w0.254: v1(80.804,29.845) 80.772,29.813 80.772,26.908 81.28,26.4 v1(81.28,20.637)
NetC13_2: C13.2@82.765,27.94 IC2.1 R16.1@89.805,20.32 | length 13.6
  Top Copper w0.254: C13.2@82.765,27.94 83.305,27.4 v4(85.3,27.4) 85.3,26.333 IC2.1@85.593,26.04 ; v4(88.7,21.6) 89.805,20.495 R16.1@89.805,20.32 R16.1@89.535,20.59
  Bottom Copper w0.254: v4(85.3,27.4) 88,24.7 88,22.3 v4(88.7,21.6)
NetC14_2: C14.2@11.22,22.288 R12.1@11.201,23.714 U3.1@13.284,26.006 | length 4.8
  Top Copper w0.254: R12.1@11.201,23.714 12.333,24.845 12.628,24.845 13.191,25.408 13.211,25.408 13.284,25.481 U3.1@13.284,26.006 ; R12.1@11.203,23.712 11.201,23.71 11.201,22.306 C14.2@11.22,22.288
NetC15_1: C15.1@120.65,41.06 R12.1@120.65,38.465 U8.1 | length 16.9
  Top Copper w0.254: U8.1@108.382,42.85 108.382,41.656 v1(108.763,41.275) ; v1(115.983,40.291) 118.691,40.291 119.358,40.958 120.548,40.958 C15.1@120.65,41.06 120.65,40.958 R12.1@120.65,38.465
  Bottom Copper w0.254: v1(108.763,41.275) 113.824,41.275 114.808,40.291 v1(115.983,40.291)
NetC17_2: C17.2@7.497,23.419 U2.8 | length 2.3
  Top Copper w0.406: C17.2@7.497,23.419 7.798,23.72 U2.8@7.798,25.578
NetC18_1: C18.1 IC1.7 V_IA_TP.TP | length 4.8
  Top Copper w0.254: IC1.7@91.1,14.57 91.93,14.57 92.7,13.8 93.935,13.8 C18.1@93.98,13.755 93.56,13.335 93.56,12.485 V_IA_TP.TP@93.662,12.383
NetC18_2: C18.2 C23.1 R23.2 | length 5
  Top Copper w0.254: R23.2@94.25,17.78 94.25,15.725 C18.2@93.98,15.455 C23.1@96.52,15.455
NetC19_2: C19.2 C24.1 R24.2 | length 5
  Top Copper w0.254: R24.2@94.25,20.32 93.98,20.59 C19.2@93.98,22.645 C24.1@96.52,22.645
NetC21_1: C21.1 U9.1 U9.4 | length 5.5
  Top Copper w0.254: U9.1@98.374,37.16 98.298,37.084 98.298,36.322 98.552,36.068 99.568,36.068 ; C21.1@99.734,34.544 99.734,35.902 99.568,36.068 ; U9.4@100.33,37.16 100.33,36.322 100.076,36.068 99.568,36.068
